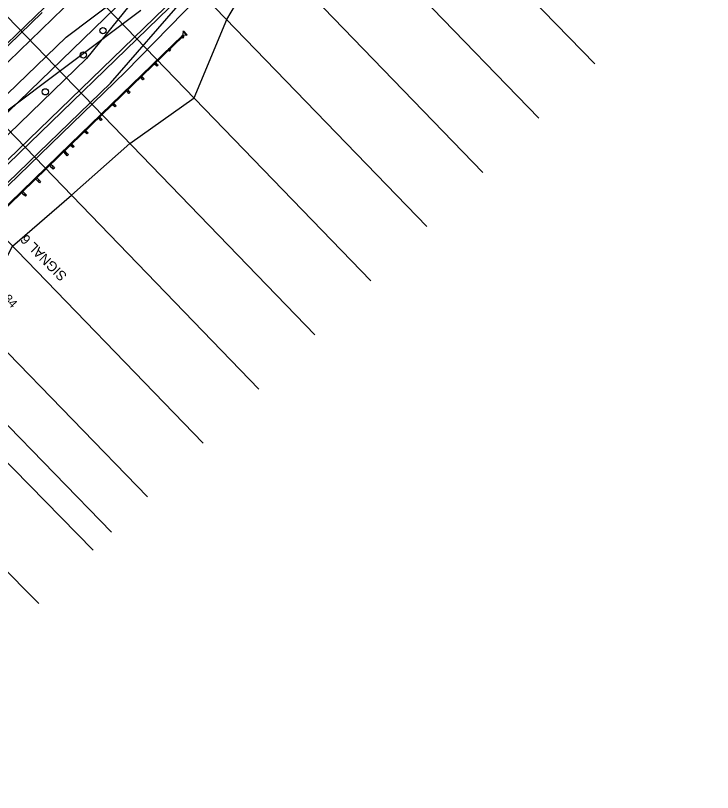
# Model space of a CAD drawing. Extents: x 2376379 to 2383101, y 559608 to 561720.
# Drawn here: x 2377223.9 to 2377447.7, y 561210.7 to 561460 of the extents above; entities that cross this region are included whole.
import ezdxf

# ---------------------------------------------------------------- set-up
doc = ezdxf.new("R2010")
doc.units = 0
for name, color, linetype in [('BR_X_SV_Bottom_of_Beam', 7, 'Continuous'), ('BR_X_SV_Deck_Top', 7, 'Continuous'), ('BR_X_SV_Pier', 7, 'Continuous'), ('DR_X_Headwall', 7, 'Continuous'), ('DT_X_Contour_Minor', 7, 'Continuous'), ('HY_X_Spring_Cells', 7, 'Continuous'), ('PM_X_CL_Dashed', 7, 'Continuous'), ('PM_X_Surveyed_Line', 7, 'Continuous'), ('PV_X_COP', 7, 'Continuous'), ('RD_X_Cells', 7, 'Continuous'), ('SV_X_Text', 7, 'Continuous')]:
    doc.layers.add(name, color=color, linetype=linetype)

msp = doc.modelspace()

# ---------------------------------------------------------------- linework, layer by layer
at = {"layer": 'BR_X_SV_Bottom_of_Beam'}
for p, q in [((2377332.62, 561553.02), (2377246.68, 561446.25)), ((2377254.33, 561438.35), (2377281.32, 561469.41)), ((2377194.11, 561395.38), (2377246.68, 561446.25)), ((2377254.33, 561438.35), (2377201.76, 561387.47))]:
    msp.add_line(p, q, dxfattribs=at)
for centre in [(2377251.91, 561455.12), (2377245.64, 561447.33), (2377233.42, 561435.51)]:
    msp.add_circle(centre, 1, dxfattribs=at)
at = {"layer": 'BR_X_SV_Deck_Top'}
for p, q in [((2377264.5, 561486.8), (2377182.46, 561407.42)), ((2377179.33, 561410.65), (2377236.22, 561465.7))]:
    msp.add_line(p, q, dxfattribs=at)
at = {"layer": 'DR_X_Headwall'}
for q in [(2377283.62, 561467.04), (2377202.28, 561386.93)]:
    msp.add_line((2377259.17, 561441.98), q, dxfattribs=at)
at = {"layer": 'DT_X_Contour_Minor'}
msp.add_line((2377291.66, 561458.74), (2377304.82, 561481.08), dxfattribs=at)
msp.add_lwpolyline([(2377210.81, 561362.63), (2377222.93, 561385.95), (2377241.81, 561402.39), (2377260.6, 561418.93), (2377281.24, 561433.55), (2377291.66, 561458.74)], dxfattribs=at)
at = {"layer": 'PM_X_CL_Dashed'}
for p, q in [((2377277.65, 561454.86), (2377277.49, 561453.55)), ((2377277.65, 561454.86), (2377277.83, 561455.04)), ((2377277.65, 561454.86), (2377278.81, 561453.67)), ((2377277.69, 561454.9), (2377278.84, 561453.7)), ((2377277.83, 561455.04), (2377278.99, 561453.84)), ((2377241.55, 561418.78), (2377277.49, 561453.55)), ((2377241.73, 561418.6), (2377277.66, 561453.37)), ((2377278.81, 561453.67), (2377277.49, 561453.55)), ((2377278.81, 561453.67), (2377278.99, 561453.84)), ((2377269.25, 561443.72), (2377268.33, 561444.68)), ((2377264.76, 561439.37), (2377263.83, 561440.33)), ((2377260.27, 561435.03), (2377259.34, 561435.99)), ((2377255.78, 561430.68), (2377254.85, 561431.64)), ((2377251.29, 561426.34), (2377250.36, 561427.3)), ((2377246.8, 561421.99), (2377245.87, 561422.95)), ((2377241.55, 561418.78), (2377205.36, 561383.75)), ((2377205.55, 561383.55), (2377241.75, 561418.58)), ((2377242.3, 561417.64), (2377241.38, 561418.6)), ((2377241.55, 561418.78), (2377242.48, 561417.82)), ((2377239.32, 561416.23), (2377239.68, 561416.58)), ((2377240.02, 561415.51), (2377239.32, 561416.23)), ((2377240.38, 561415.86), (2377239.68, 561416.58)), ((2377234.83, 561411.88), (2377235.19, 561412.23)), ((2377235.53, 561411.16), (2377234.83, 561411.88)), ((2377235.89, 561411.51), (2377235.19, 561412.23)), ((2377230.34, 561407.54), (2377230.7, 561407.88)), ((2377231.04, 561406.82), (2377230.34, 561407.54)), ((2377231.4, 561407.17), (2377230.7, 561407.88)), ((2377225.85, 561403.19), (2377226.21, 561403.54)), ((2377226.55, 561402.47), (2377225.85, 561403.19)), ((2377226.9, 561402.82), (2377226.21, 561403.54))]:
    msp.add_line(p, q, dxfattribs=at)
for points in [[(2377277.13, 561453.2), (2377277.49, 561453.55), (2377277.95, 561453.07), (2377277.59, 561452.72)], [(2377272.82, 561449.03), (2377273.18, 561449.37), (2377273.64, 561448.89), (2377273.28, 561448.55)], [(2377268.33, 561444.68), (2377268.68, 561445.03), (2377269.15, 561444.55), (2377268.79, 561444.2)], [(2377268.79, 561444.2), (2377269.15, 561444.55), (2377269.61, 561444.07), (2377269.25, 561443.72)], [(2377263.83, 561440.33), (2377264.19, 561440.68), (2377264.66, 561440.2), (2377264.3, 561439.85)], [(2377264.3, 561439.85), (2377264.66, 561440.2), (2377265.12, 561439.72), (2377264.76, 561439.37)], [(2377259.34, 561435.99), (2377259.7, 561436.33), (2377260.16, 561435.85), (2377259.81, 561435.51)], [(2377259.81, 561435.51), (2377260.16, 561435.85), (2377260.63, 561435.37), (2377260.27, 561435.03)], [(2377254.85, 561431.64), (2377255.21, 561431.99), (2377255.67, 561431.51), (2377255.31, 561431.16)], [(2377255.31, 561431.16), (2377255.67, 561431.51), (2377256.14, 561431.03), (2377255.78, 561430.68)], [(2377250.36, 561427.3), (2377250.72, 561427.64), (2377251.18, 561427.16), (2377250.82, 561426.82)], [(2377250.82, 561426.82), (2377251.18, 561427.16), (2377251.65, 561426.68), (2377251.29, 561426.34)], [(2377245.87, 561422.95), (2377246.23, 561423.3), (2377246.69, 561422.82), (2377246.33, 561422.47)], [(2377246.33, 561422.47), (2377246.69, 561422.82), (2377247.15, 561422.34), (2377246.8, 561421.99)], [(2377241.38, 561418.6), (2377241.73, 561418.95), (2377242.2, 561418.47), (2377241.84, 561418.12)], [(2377241.84, 561418.12), (2377242.2, 561418.47), (2377242.66, 561417.99), (2377242.3, 561417.64)], [(2377240.84, 561415.38), (2377240.48, 561415.03), (2377240.02, 561415.51), (2377240.38, 561415.86)], [(2377236.35, 561411.03), (2377235.99, 561410.68), (2377235.53, 561411.16), (2377235.89, 561411.51)], [(2377231.86, 561406.69), (2377231.5, 561406.34), (2377231.04, 561406.82), (2377231.4, 561407.17)], [(2377227.37, 561402.34), (2377227.01, 561401.99), (2377226.55, 561402.47), (2377226.9, 561402.82)]]:
    msp.add_lwpolyline(points, close=True, dxfattribs=at)
at = {"layer": 'PM_X_Surveyed_Line'}
for p, q in [((2377242.95, 561616.93), (2377409.84, 561444.45)), ((2377391.88, 561427.06), (2377224.99, 561599.54)), ((2377207.02, 561582.16), (2377373.91, 561409.68)), ((2377355.94, 561392.3), (2377189.05, 561564.77)), ((2377171.09, 561547.39), (2377337.98, 561374.91)), ((2377320.01, 561357.53), (2377153.12, 561530)), ((2377135.16, 561512.62), (2377302.04, 561340.14)), ((2377284.08, 561322.76), (2377117.19, 561495.24)), ((2377099.07, 561477.69), (2377266.28, 561305.53)), ((2377087, 561465.93), (2377254.71, 561294.25)), ((2377080.8, 561459.86), (2377248.76, 561288.43)), ((2377231.31, 561271.27), (2377062.6, 561441.96))]:
    msp.add_line(p, q, dxfattribs=at)
at = {"layer": 'PV_X_COP'}
for p, q in [((2377240.08, 561453.08), (2377349.7, 561535.37)), ((2377206.54, 561418.54), (2377264.14, 561461.75)), ((2377179.85, 561410.11), (2377232.43, 561460.98)), ((2377187.5, 561402.21), (2377240.08, 561453.08))]:
    msp.add_line(p, q, dxfattribs=at)
at = {"layer": 'RD_X_Cells'}
for p, q in [((2376995.66, 561210.67), (2377447.66, 561648.02)), ((2377190.46, 561399.15), (2377411.73, 561613.26))]:
    msp.add_line(p, q, dxfattribs=at)
at = {"layer": 'SV_X_Text'}
for p, q in [((2377280.15, 561470.63), (2377198.11, 561391.25)), ((2377280.84, 561469.91), (2377198.8, 561390.53))]:
    msp.add_line(p, q, dxfattribs=at)

# ---------------------------------------------------------------- texts
at = {"layer": 'BR_X_SV_Pier'}
msp.add_text('SIGNAL 6', height=3.125, rotation=134.64, dxfattribs=at).set_placement((2377240.6, 561376.64))
at = {"layer": 'HY_X_Spring_Cells'}
msp.add_text('2790+60.84', height=2.8, rotation=314.0565, dxfattribs=at).set_placement((2377208.86, 561380.2))

doc.saveas('drawing.dxf')
